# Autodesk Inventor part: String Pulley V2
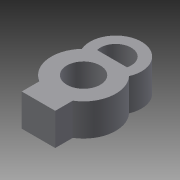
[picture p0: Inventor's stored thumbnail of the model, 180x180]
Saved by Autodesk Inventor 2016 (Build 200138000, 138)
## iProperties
Created: 2013-12
Part Number: String Pulley V2
Material: Generic
Document SubType Name: Modeling
Designer: 603839
Density: 1 g/cm^3
Appearance: Default
Author: 603839
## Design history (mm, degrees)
sketch "Sketch1"
  geometry: C1 r 3.302 at (0, 0); C2 r 6.35 at (0, 0); 1 further point
  constraints: 2 centre point, 2 coincident
  dimensions: "d0" = 6.604 diameter of C1; "d1" = 12.7 diameter of C2
extrude "Extrusion1" new body sketch "Sketch1" distance "d2" = 6.35; taper "d3" = 0 deg
sketch "Sketch3"
  geometry: L1 (-3.302, 0)-(-3.302, -8.89); L2 (3.302, 0)-(3.302, -8.89); L3 (3.302, -8.89)-(-3.302, -8.89); A1 r 3.302 centre (0, 0) between (-3.302, 0) and (3.302, 0) reference
  constraints: 6 end point, 2 point on circle, 2 tangent, 1 parallel, 1 vertical
  dimensions: "d4" = 8.89 distance of L1.start L1.end; "d5" = 8.89 distance of L2.start L2.end
extrude "Extrusion2" join sketch "Sketch3" stored distance "d6" = 6.35; taper "d7" = 0 deg
sketch "Sketch4"
  geometry: C1 r 3.302 at (0, 0) reference; A1 r 6.35 centre (0, 0) between (3.302, -5.424) and (-3.302, -5.424) reference; A2 r 3.048 centre (0, 6.35) between (2.959, 5.618) and (-2.959, 5.618); A3 r 5.08 centre (0, 6.35) between (4.656, 4.318) and (-4.656, 4.318); A4 r 6.35 centre (0, 0) between (-2.959, 5.618) and (-4.656, 4.318); A5 r 6.35 centre (0, 0) between (4.656, 4.318) and (2.959, 5.618)
  constraints: 14 point on circle, 4 centre point, 2 concentric, 1 tangent
  dimensions: "d9" = 10.16 diameter of A3
extrude "Extrusion3" join sketch "Sketch4" stored distance "d10" = 6.35; taper "d11" = 0 deg
sketch "Sketch5"
  geometry: L1 (3.302, -8.89)-(3.302, -5.424) reference; L2 (-2.959, 5.618)-(2.959, 5.618); A1 r 6.35 centre (0, 0) between (2.959, 5.618) and (-2.959, 5.618) reference
  constraints: 2 end point, 1 perpendicular
extrude "Extrusion4" cut sketch "Sketch5" distance "d12" = 6.35; taper "d13" = 0 deg
body "Solid1"
